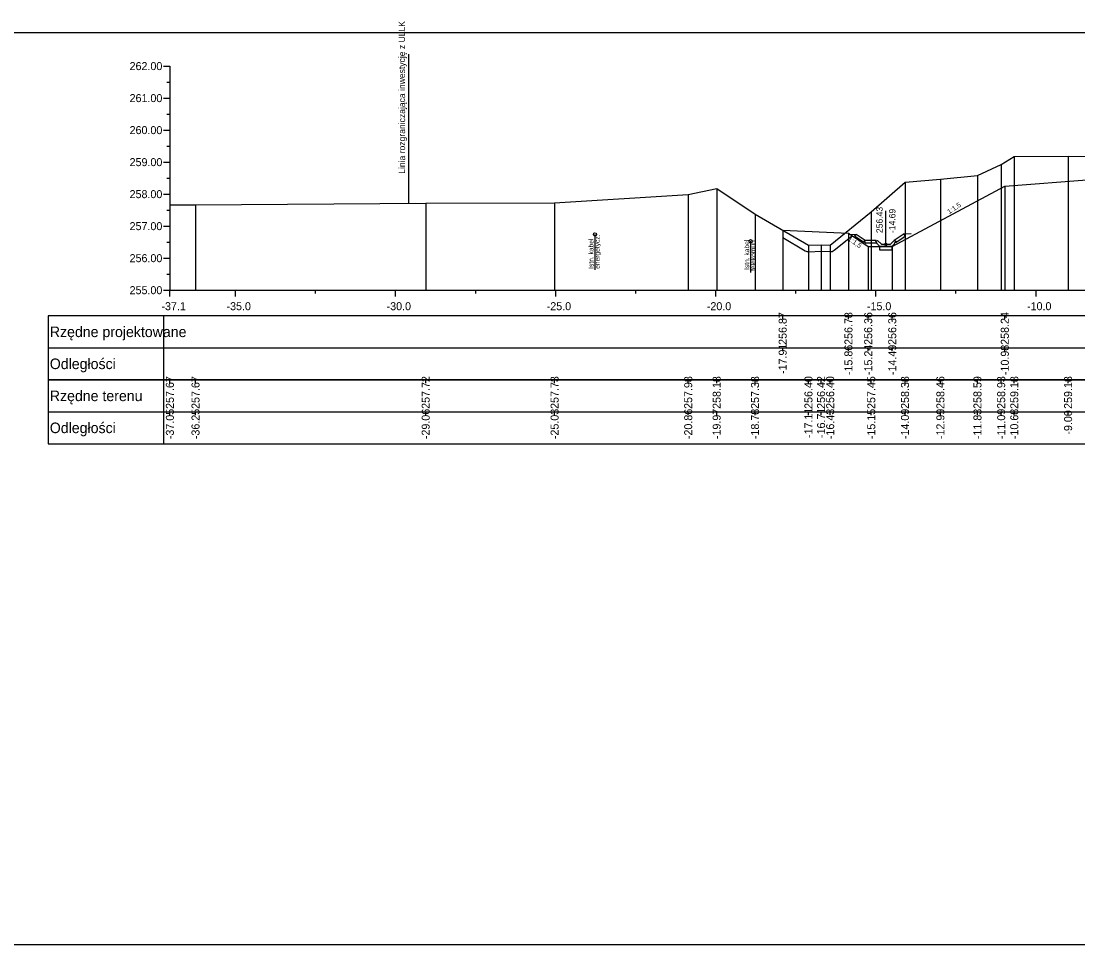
# Model space of a CAD drawing. Extents: x 6516023 to 6560129, y 5513077 to 5529206.
# Drawn here: x 6516445.82 to 6516478.82, y 5514551.66 to 5514580.51 of the extents above; entities that cross this region are included whole.
import ezdxf

# ---------------------------------------------------------------- set-up
doc = ezdxf.new("R2010")
doc.units = 0
for name, color, linetype in [('IR_default', 7, 'Continuous'), ('TOR_PRZEK_P-kable', 7, 'Continuous'), ('TOR_PRZEK_P-odwodnienie', 7, 'Continuous'), ('TOR_PRZEK_P-opisy', 7, 'Continuous'), ('TOR_PRZEK_P-schodkowanie+wymiana', 7, 'Continuous'), ('TOR_PRZEK_P-tabelka istniejace', 7, 'Continuous'), ('TOR_PRZEK_P-tabelka projektowane', 7, 'Continuous'), ('TOR_PRZEK_P-teren istniejacy', 7, 'Continuous'), ('TOR_PRZEK_P-uklad odniesienia', 7, 'Continuous'), ('TOR_PRZEK_P-warstwa ochronna II', 7, 'Continuous'), ('TOR_PS_T-granica PKP-projektowana', 7, 'Continuous'), ('TOR_RAMKI-ramka+tabelka 1', 7, 'Continuous')]:
    doc.layers.add(name, color=color, linetype=linetype)

msp = doc.modelspace()

# ---------------------------------------------------------------- linework, layer by layer
at = {"layer": 'IR_default'}
msp.add_lwpolyline([(6516469.601, 5514573.979), (6516471.655, 5514573.882), (6516472.273, 5514573.47), (6516473.023, 5514573.47), (6516476.538, 5514575.351), (6516479.234, 5514575.559)], dxfattribs=at)
at = {"layer": 'TOR_PRZEK_P-kable'}
for p, q in [((6516463.738, 5514573.847), (6516463.738, 5514572.737)), ((6516468.601, 5514573.636), (6516468.601, 5514572.663))]:
    msp.add_line(p, q, dxfattribs=at)
for centre in [(6516463.738, 5514573.847), (6516468.601, 5514573.636)]:
    msp.add_circle(centre, 0.05, dxfattribs=at)
at = {"layer": 'TOR_PRZEK_P-odwodnienie'}
for p, q in [((6516472.823, 5514573.54), (6516472.823, 5514574.584)), ((6516472.131, 5514573.595), (6516471.87, 5514573.769)), ((6516472.176, 5514573.662), (6516471.895, 5514573.849)), ((6516472.143, 5514573.612), (6516472.131, 5514573.595)), ((6516472.176, 5514573.662), (6516472.167, 5514573.649)), ((6516472.521, 5514573.66), (6516472.184, 5514573.66)), ((6516472.521, 5514573.58), (6516472.207, 5514573.58)), ((6516472.515, 5514573.635), (6516472.563, 5514573.659)), ((6516472.521, 5514573.66), (6516472.521, 5514573.645)), ((6516472.521, 5514573.6), (6516472.521, 5514573.58)), ((6516472.683, 5514573.54), (6516472.563, 5514573.659)), ((6516472.963, 5514573.54), (6516473.083, 5514573.659)), ((6516473.083, 5514573.659), (6516473.13, 5514573.635)), ((6516473.087, 5514573.665), (6516473.368, 5514573.852)), ((6516473.087, 5514573.665), (6516473.096, 5514573.653)), ((6516473.121, 5514573.615), (6516473.132, 5514573.599)), ((6516473.132, 5514573.599), (6516473.393, 5514573.773)), ((6516472.633, 5514573.47), (6516473.013, 5514573.47)), ((6516472.683, 5514573.54), (6516472.963, 5514573.54))]:
    msp.add_line(p, q, dxfattribs=at)
for points in [[(6516471.69, 5514573.858), (6516471.895, 5514573.849)], [(6516471.845, 5514573.822), (6516471.895, 5514573.849)], [(6516471.845, 5514573.822), (6516471.87, 5514573.769)], [(6516472.167, 5514573.649), (6516472.132, 5514573.631)], [(6516472.132, 5514573.631), (6516472.143, 5514573.612)], [(6516472.157, 5514573.61), (6516472.184, 5514573.66)], [(6516472.157, 5514573.61), (6516472.207, 5514573.58)], [(6516472.521, 5514573.645), (6516472.502, 5514573.61)], [(6516472.502, 5514573.61), (6516472.521, 5514573.6)], [(6516472.563, 5514573.54), (6516472.515, 5514573.635)], [(6516473.083, 5514573.54), (6516473.13, 5514573.635)], [(6516473.096, 5514573.653), (6516473.131, 5514573.634)], [(6516473.131, 5514573.634), (6516473.121, 5514573.615)], [(6516473.614, 5514573.864), (6516473.368, 5514573.852)], [(6516473.418, 5514573.826), (6516473.368, 5514573.852)], [(6516473.418, 5514573.826), (6516473.393, 5514573.773)], [(6516472.273, 5514573.47), (6516472.272, 5514573.47), (6516472.273, 5514573.47), (6516472.272, 5514573.469), (6516472.273, 5514573.47), (6516472.273, 5514573.469), (6516472.273, 5514573.47), (6516472.273, 5514573.47)], [(6516472.633, 5514573.47), (6516472.563, 5514573.54)], [(6516473.023, 5514573.47), (6516472.623, 5514573.47), (6516472.623, 5514573.37), (6516473.023, 5514573.37), (6516473.023, 5514573.47)], [(6516473.013, 5514573.47), (6516473.083, 5514573.54)], [(6516473.023, 5514573.47), (6516473.022, 5514573.47), (6516473.023, 5514573.47), (6516473.022, 5514573.469), (6516473.023, 5514573.47), (6516473.023, 5514573.469), (6516473.023, 5514573.47), (6516473.023, 5514573.47)]]:
    msp.add_lwpolyline(points, dxfattribs=at)
msp.add_circle((6516472.823, 5514573.54), 0.035, dxfattribs=at)
at = {"layer": 'TOR_PRZEK_P-schodkowanie+wymiana'}
for p, q in [((6516469.601, 5514573.747), (6516470.305, 5514573.336)), ((6516471.212, 5514573.354), (6516471.766, 5514573.807))]:
    msp.add_line(p, q, dxfattribs=at)
msp.add_lwpolyline([(6516470.413, 5514573.309), (6516470.799, 5514573.323), (6516471.076, 5514573.31)], dxfattribs=at)
for centre, start, end in [((6516470.406, 5514573.509), 239.6774, 272.0806), ((6516471.085, 5514573.509), 267.2593, 309.2323)]:
    msp.add_arc(centre, 0.2, start, end, dxfattribs=at)
at = {"layer": 'TOR_PRZEK_P-tabelka istniejace'}
for p, q in [((6516446.663, 5514569.306), (6516446.663, 5514567.306)), ((6516450.263, 5514569.306), (6516450.263, 5514567.306)), ((6516450.463, 5514569.206), (6516450.463, 5514569.306)), ((6516451.264, 5514569.206), (6516451.264, 5514569.306)), ((6516458.452, 5514569.206), (6516458.452, 5514569.306)), ((6516462.478, 5514569.206), (6516462.478, 5514569.306)), ((6516466.651, 5514569.206), (6516466.651, 5514569.306)), ((6516467.54, 5514569.206), (6516467.54, 5514569.306)), ((6516468.737, 5514569.206), (6516468.737, 5514569.306)), ((6516470.406, 5514569.206), (6516470.406, 5514569.306)), ((6516470.8, 5514569.206), (6516470.8, 5514569.306)), ((6516471.085, 5514569.206), (6516471.085, 5514569.306)), ((6516472.367, 5514569.206), (6516472.367, 5514569.306)), ((6516473.421, 5514569.206), (6516473.421, 5514569.306)), ((6516474.526, 5514569.206), (6516474.526, 5514569.306)), ((6516475.684, 5514569.206), (6516475.684, 5514569.306)), ((6516476.425, 5514569.206), (6516476.425, 5514569.306)), ((6516476.834, 5514569.206), (6516476.834, 5514569.306)), ((6516478.514, 5514569.206), (6516478.514, 5514569.306)), ((6516446.663, 5514568.306), (6516525.463, 5514568.306)), ((6516450.463, 5514568.206), (6516450.463, 5514568.306)), ((6516451.264, 5514568.206), (6516451.264, 5514568.306)), ((6516458.452, 5514568.206), (6516458.452, 5514568.306)), ((6516462.478, 5514568.206), (6516462.478, 5514568.306)), ((6516466.651, 5514568.206), (6516466.651, 5514568.306)), ((6516467.54, 5514568.206), (6516467.54, 5514568.306)), ((6516468.737, 5514568.206), (6516468.737, 5514568.306)), ((6516470.406, 5514568.206), (6516470.406, 5514568.306)), ((6516470.8, 5514568.206), (6516470.8, 5514568.306)), ((6516471.085, 5514568.206), (6516471.085, 5514568.306)), ((6516472.367, 5514568.206), (6516472.367, 5514568.306)), ((6516473.421, 5514568.206), (6516473.421, 5514568.306)), ((6516474.526, 5514568.206), (6516474.526, 5514568.306)), ((6516475.684, 5514568.206), (6516475.684, 5514568.306)), ((6516476.425, 5514568.206), (6516476.425, 5514568.306)), ((6516476.834, 5514568.206), (6516476.834, 5514568.306)), ((6516478.514, 5514568.206), (6516478.514, 5514568.306))]:
    msp.add_line(p, q, dxfattribs=at)
for points in [[(6516476.834, 5514576.285), (6516476.834, 5514572.306), (6516476.834, 5514572.176), (6516476.834, 5514572.106)], [(6516478.514, 5514576.289), (6516478.514, 5514572.306), (6516478.514, 5514572.176), (6516478.514, 5514572.106)], [(6516476.425, 5514576.034), (6516476.425, 5514572.306), (6516476.425, 5514572.176), (6516476.425, 5514572.106)], [(6516474.526, 5514575.57), (6516474.526, 5514572.306), (6516474.526, 5514572.176), (6516474.526, 5514572.106)], [(6516475.684, 5514575.692), (6516475.684, 5514572.306), (6516475.684, 5514572.176), (6516475.684, 5514572.106)], [(6516467.54, 5514575.281), (6516467.54, 5514572.306), (6516467.54, 5514572.176), (6516467.54, 5514572.106)], [(6516473.421, 5514575.484), (6516473.421, 5514572.306), (6516473.421, 5514572.176), (6516473.421, 5514572.106)], [(6516466.651, 5514575.091), (6516466.651, 5514572.306), (6516466.651, 5514572.176), (6516466.651, 5514572.106)], [(6516450.463, 5514574.771), (6516450.463, 5514572.306), (6516450.463, 5514572.176), (6516450.463, 5514572.106)], [(6516451.264, 5514574.777), (6516451.264, 5514572.306), (6516451.264, 5514572.176), (6516451.264, 5514572.106)], [(6516458.452, 5514574.824), (6516458.452, 5514572.306), (6516458.452, 5514572.176), (6516458.452, 5514572.106)], [(6516462.478, 5514574.838), (6516462.478, 5514572.306), (6516462.478, 5514572.176), (6516462.478, 5514572.106)], [(6516472.367, 5514574.556), (6516472.367, 5514572.306), (6516472.367, 5514572.176), (6516472.367, 5514572.106)], [(6516468.737, 5514574.485), (6516468.737, 5514572.306), (6516468.737, 5514572.176), (6516468.737, 5514572.106)], [(6516470.406, 5514573.509), (6516470.406, 5514572.306), (6516470.406, 5514572.176), (6516470.406, 5514572.106)], [(6516470.8, 5514573.523), (6516470.8, 5514572.306), (6516470.8, 5514572.176), (6516470.8, 5514572.106)], [(6516471.085, 5514573.509), (6516471.085, 5514572.306), (6516471.085, 5514572.176), (6516471.085, 5514572.106)]]:
    msp.add_lwpolyline(points, dxfattribs=at)
msp.add_lwpolyline([(6516446.663, 5514569.306), (6516446.663, 5514567.306), (6516525.463, 5514567.306), (6516525.463, 5514569.306)], close=True, dxfattribs=at)
at = {"layer": 'TOR_PRZEK_P-tabelka projektowane'}
for p, q in [((6516446.663, 5514571.306), (6516446.663, 5514569.306)), ((6516450.263, 5514571.306), (6516450.263, 5514569.306)), ((6516469.601, 5514571.206), (6516469.601, 5514571.306)), ((6516471.655, 5514571.206), (6516471.655, 5514571.306)), ((6516472.273, 5514571.206), (6516472.273, 5514571.306)), ((6516473.023, 5514571.206), (6516473.023, 5514571.306)), ((6516476.538, 5514571.206), (6516476.538, 5514571.306)), ((6516446.663, 5514570.306), (6516525.463, 5514570.306)), ((6516469.601, 5514570.206), (6516469.601, 5514570.306)), ((6516471.655, 5514570.206), (6516471.655, 5514570.306)), ((6516472.273, 5514570.206), (6516472.273, 5514570.306)), ((6516473.023, 5514570.206), (6516473.023, 5514570.306)), ((6516476.538, 5514570.206), (6516476.538, 5514570.306))]:
    msp.add_line(p, q, dxfattribs=at)
for points in [[(6516476.538, 5514575.351), (6516476.538, 5514572.306), (6516476.538, 5514572.176), (6516476.538, 5514572.106)], [(6516469.601, 5514573.979), (6516469.601, 5514572.306), (6516469.601, 5514572.176), (6516469.601, 5514572.106)], [(6516471.655, 5514573.882), (6516471.655, 5514572.306), (6516471.655, 5514572.176), (6516471.655, 5514572.106)], [(6516472.273, 5514573.47), (6516472.273, 5514572.306), (6516472.273, 5514572.176), (6516472.273, 5514572.106)], [(6516473.023, 5514573.47), (6516473.023, 5514572.306), (6516473.023, 5514572.176), (6516473.023, 5514572.106)]]:
    msp.add_lwpolyline(points, dxfattribs=at)
msp.add_lwpolyline([(6516446.663, 5514571.306), (6516446.663, 5514569.306), (6516525.463, 5514569.306), (6516525.463, 5514571.306)], close=True, dxfattribs=at)
at = {"layer": 'TOR_PRZEK_P-teren istniejacy'}
msp.add_lwpolyline([(6516450.463, 5514574.771), (6516451.264, 5514574.777), (6516458.452, 5514574.824), (6516462.478, 5514574.838), (6516466.651, 5514575.091), (6516467.54, 5514575.281), (6516468.737, 5514574.485), (6516470.406, 5514573.509), (6516470.8, 5514573.523), (6516471.085, 5514573.509), (6516472.367, 5514574.556), (6516473.421, 5514575.484), (6516474.526, 5514575.57), (6516475.684, 5514575.692), (6516476.425, 5514576.034), (6516476.834, 5514576.285), (6516478.514, 5514576.289), (6516480.201, 5514576.279)], dxfattribs=at)
at = {"layer": 'TOR_PRZEK_P-uklad odniesienia'}
for p, q in [((6516450.263, 5514579.106), (6516450.463, 5514579.106)), ((6516450.463, 5514579.106), (6516450.463, 5514572.106)), ((6516450.363, 5514578.606), (6516450.463, 5514578.606)), ((6516450.263, 5514578.106), (6516450.463, 5514578.106)), ((6516450.363, 5514577.606), (6516450.463, 5514577.606)), ((6516450.263, 5514577.106), (6516450.463, 5514577.106)), ((6516450.363, 5514576.606), (6516450.463, 5514576.606)), ((6516450.263, 5514576.106), (6516450.463, 5514576.106)), ((6516450.363, 5514575.606), (6516450.463, 5514575.606)), ((6516450.263, 5514575.106), (6516450.463, 5514575.106)), ((6516450.363, 5514574.606), (6516450.463, 5514574.606)), ((6516450.263, 5514574.106), (6516450.463, 5514574.106)), ((6516450.363, 5514573.606), (6516450.463, 5514573.606)), ((6516450.263, 5514573.106), (6516450.463, 5514573.106)), ((6516450.363, 5514572.606), (6516450.463, 5514572.606)), ((6516450.263, 5514572.106), (6516450.463, 5514572.106)), ((6516450.463, 5514572.106), (6516525.463, 5514572.106)), ((6516450.463, 5514572.006), (6516450.463, 5514572.106)), ((6516450.463, 5514571.906), (6516450.463, 5514572.106)), ((6516452.513, 5514571.906), (6516452.513, 5514572.106)), ((6516455.013, 5514572.006), (6516455.013, 5514572.106)), ((6516457.513, 5514571.906), (6516457.513, 5514572.106)), ((6516460.013, 5514572.006), (6516460.013, 5514572.106)), ((6516462.513, 5514571.906), (6516462.513, 5514572.106)), ((6516465.013, 5514572.006), (6516465.013, 5514572.106)), ((6516467.513, 5514571.906), (6516467.513, 5514572.106)), ((6516470.013, 5514572.006), (6516470.013, 5514572.106)), ((6516472.513, 5514571.906), (6516472.513, 5514572.106)), ((6516475.013, 5514572.006), (6516475.013, 5514572.106)), ((6516477.513, 5514571.906), (6516477.513, 5514572.106))]:
    msp.add_line(p, q, dxfattribs=at)
at = {"layer": 'TOR_PRZEK_P-warstwa ochronna II'}
msp.add_lwpolyline([(6516469.601, 5514573.979), (6516471.655, 5514573.882), (6516472.273, 5514573.47), (6516473.023, 5514573.47), (6516476.538, 5514575.351), (6516479.234, 5514575.559), (6516479.713, 5514575.878), (6516480.313, 5514575.902), (6516488.263, 5514576.222), (6516489.538, 5514576.271), (6516490.813, 5514576.22), (6516498.711, 5514575.904), (6516499.313, 5514575.88), (6516499.792, 5514575.561), (6516501.613, 5514575.388), (6516503.573, 5514574.081), (6516504.053, 5514573.761), (6516504.453, 5514573.761), (6516506.147, 5514574.891)], dxfattribs=at)
at = {"layer": 'TOR_PS_T-granica PKP-projektowana'}
msp.add_line((6516457.921, 5514574.82), (6516457.921, 5514579.478), dxfattribs=at)
at = {"layer": 'TOR_RAMKI-ramka+tabelka 1'}
msp.add_lwpolyline([(6516362.013, 5514580.156), (6516609.513, 5514580.156), (6516609.513, 5514551.656), (6516362.013, 5514551.656)], close=True, dxfattribs=at)

# ---------------------------------------------------------------- texts
at = {"layer": 'TOR_PRZEK_P-kable'}
for s, height, p in [('Istn. kabel', 0.14999, (6516463.693, 5514572.774)), ('energetycz.', 0.14999, (6516463.887, 5514572.774)), ('Istn. kabel', 0.14999, (6516468.556, 5514572.739)), ('telekomun.', 0.15, (6516468.751, 5514572.71))]:
    msp.add_text(s, height=height, rotation=90.0511, dxfattribs=at).set_placement(p)
at = {"layer": 'TOR_PRZEK_P-odwodnienie'}
for s, p in [('256.43', (6516472.723, 5514573.89)), ('-14.69', (6516473.123, 5514573.89))]:
    msp.add_text(s, height=0.2, rotation=90, dxfattribs=at).set_placement(p)
at = {"layer": 'TOR_PRZEK_P-opisy'}
for rotation, p in [(34.0701, (6516474.803, 5514574.478)), (325.9299, (6516471.622, 5514573.671))]:
    msp.add_text('1:1,5', height=0.15, rotation=rotation, dxfattribs=at).set_placement(p)
at = {"layer": 'TOR_PRZEK_P-tabelka istniejace'}
for s, p in [('257.67', (6516450.588, 5514568.398)), ('257.67', (6516451.389, 5514568.398)), ('257.72', (6516458.577, 5514568.4)), ('257.73', (6516462.603, 5514568.398)), ('257.98', (6516466.776, 5514568.398)), ('258.18', (6516467.665, 5514568.398)), ('257.38', (6516468.862, 5514568.398)), ('256.40', (6516470.531, 5514568.398)), ('256.42', (6516470.925, 5514568.4)), ('256.40', (6516471.21, 5514568.398)), ('257.45', (6516472.492, 5514568.397)), ('258.38', (6516473.546, 5514568.398)), ('258.46', (6516474.651, 5514568.398)), ('258.59', (6516475.809, 5514568.398)), ('258.93', (6516476.55, 5514568.398)), ('259.18', (6516476.959, 5514568.398)), ('259.18', (6516478.639, 5514568.398)), ('-37.05', (6516450.588, 5514567.453)), ('-36.25', (6516451.389, 5514567.453)), ('-29.06', (6516458.577, 5514567.454)), ('-25.03', (6516462.603, 5514567.454)), ('-20.86', (6516466.776, 5514567.454)), ('-19.97', (6516467.665, 5514567.455)), ('-18.78', (6516468.862, 5514567.454)), ('-17.11', (6516470.531, 5514567.489)), ('-16.71', (6516470.925, 5514567.489)), ('-16.43', (6516471.21, 5514567.454)), ('-15.15', (6516472.492, 5514567.453)), ('-14.09', (6516473.546, 5514567.455)), ('-12.99', (6516474.651, 5514567.455)), ('-11.83', (6516475.809, 5514567.454)), ('-11.09', (6516476.55, 5514567.455)), ('-10.68', (6516476.959, 5514567.454)), ('-9.00', (6516478.639, 5514567.594))]:
    msp.add_text(s, height=0.25, rotation=90, dxfattribs=at).set_placement(p)
for s, p in [('Rzędne terenu', (6516446.713, 5514568.641)), ('Odległości', (6516446.713, 5514567.641))]:
    msp.add_text(s, height=0.33, dxfattribs=at).set_placement(p)
at = {"layer": 'TOR_PRZEK_P-tabelka projektowane'}
for s, p in [('256.87', (6516469.726, 5514570.398)), ('256.78', (6516471.78, 5514570.398)), ('256.36', (6516472.398, 5514570.398)), ('256.36', (6516473.148, 5514570.398)), ('258.24', (6516476.663, 5514570.399)), ('-17.91', (6516469.726, 5514569.489)), ('-15.86', (6516471.78, 5514569.454)), ('-15.24', (6516472.398, 5514569.455)), ('-14.49', (6516473.148, 5514569.455)), ('-10.98', (6516476.663, 5514569.454))]:
    msp.add_text(s, height=0.25, rotation=90, dxfattribs=at).set_placement(p)
for s, p in [('Rzędne projektowane', (6516446.713, 5514570.641)), ('Odległości', (6516446.713, 5514569.641))]:
    msp.add_text(s, height=0.33, dxfattribs=at).set_placement(p)
at = {"layer": 'TOR_PRZEK_P-uklad odniesienia'}
for s, height, p in [('262.00', 0.25, (6516449.205, 5514578.981)), ('261.00', 0.25, (6516449.205, 5514577.981)), ('260.00', 0.25, (6516449.205, 5514576.981)), ('259.00', 0.25, (6516449.205, 5514575.981)), ('258.00', 0.25, (6516449.205, 5514574.981)), ('257.00', 0.25, (6516449.205, 5514573.981)), ('256.00', 0.25, (6516449.205, 5514572.981)), ('255.00', 0.25, (6516449.205, 5514571.981)), ('-', 0.0001, (6516450.463, 5514572.106)), ('-37.1', 0.25, (6516450.199, 5514571.481)), ('-35.0', 0.25, (6516452.232, 5514571.481)), ('-30.0', 0.25, (6516457.232, 5514571.481)), ('-25.0', 0.25, (6516462.232, 5514571.481)), ('-20.0', 0.25, (6516467.232, 5514571.481)), ('-15.0', 0.25, (6516472.232, 5514571.481)), ('-10.0', 0.25, (6516477.232, 5514571.481))]:
    msp.add_text(s, height=height, dxfattribs=at).set_placement(p)
at = {"layer": 'TOR_PS_T-granica PKP-projektowana'}
msp.add_text('Linia rozgraniczająca inwestycję z ULLK', height=0.2, rotation=90.0511, dxfattribs=at).set_placement((6516457.811, 5514575.742))

doc.saveas('drawing.dxf')
